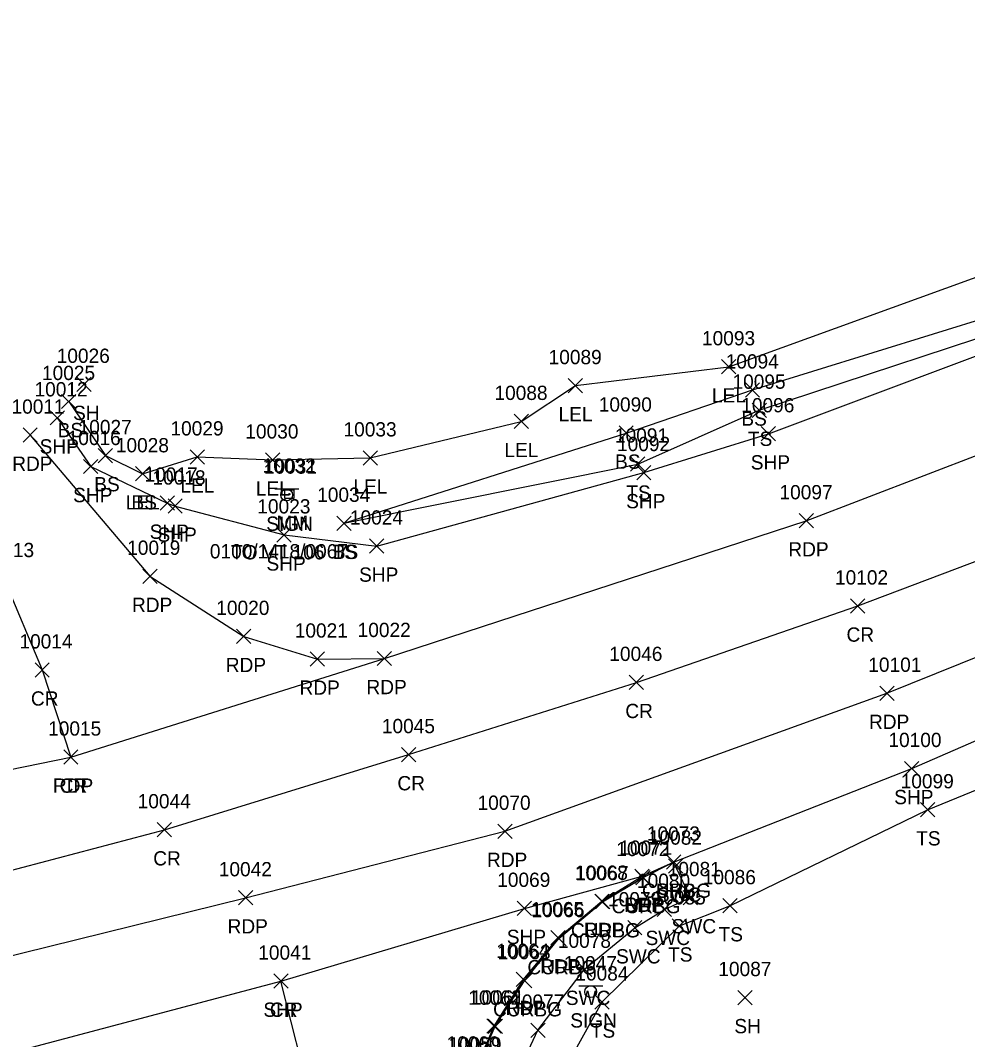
# Model space of a CAD drawing. Extents: x 1611797 to 1633212, y 298978 to 305475.
# Drawn here: x 1631296.3 to 1631428.9, y 304778.9 to 304921.6 of the extents above; entities that cross this region are included whole.
import ezdxf

# ---------------------------------------------------------------- set-up
doc = ezdxf.new("R2010")
doc.units = 0
for name, color, linetype in [('L_A', 7, 'Continuous'), ('L_I', 7, 'Continuous'), ('L_TIC', 7, 'Continuous'), ('LARO', 7, 'Continuous'), ('LELB', 7, 'Continuous'), ('P_A', 7, 'Continuous'), ('P_I', 7, 'Continuous'), ('P_TIC', 7, 'Continuous'), ('PET', 7, 'Continuous'), ('PRC', 7, 'Continuous'), ('PSP', 7, 'Continuous'), ('R_A', 7, 'Continuous'), ('R_I', 7, 'Continuous'), ('R_TIC', 7, 'Continuous'), ('RC', 7, 'Continuous'), ('RSW', 7, 'Continuous'), ('S_A', 7, 'Continuous'), ('S_C', 7, 'Continuous'), ('S_I', 7, 'Continuous'), ('SRM', 7, 'Continuous'), ('SSGN', 7, 'Continuous')]:
    doc.layers.add(name, color=color, linetype=linetype)

msp = doc.modelspace()

# ---------------------------------------------------------------- linework, layer by layer
at = {"layer": 'L_TIC'}
for points in [[(1631394.47, 304872.14), (1631396.47, 304874.14)], [(1631396.47, 304872.14), (1631394.47, 304874.14)], [(1631304.15, 304869.68), (1631306.15, 304871.68)], [(1631306.15, 304869.68), (1631304.15, 304871.68)], [(1631372.99, 304869.5), (1631374.99, 304871.5)], [(1631374.99, 304869.5), (1631372.99, 304871.5)], [(1631397.79, 304868.89), (1631399.79, 304870.89)], [(1631399.79, 304868.89), (1631397.79, 304870.89)], [(1631302.03, 304867.28), (1631304.03, 304869.28)], [(1631304.03, 304867.28), (1631302.03, 304869.28)], [(1631398.74, 304866.06), (1631400.74, 304868.06)], [(1631400.74, 304866.06), (1631398.74, 304868.06)], [(1631365.4, 304864.49), (1631367.4, 304866.49)], [(1631367.4, 304864.49), (1631365.4, 304866.49)], [(1631380.1, 304862.86), (1631382.1, 304864.86)], [(1631382.1, 304862.86), (1631380.1, 304864.86)], [(1631307.16, 304859.7), (1631309.16, 304861.7)], [(1631309.16, 304859.7), (1631307.16, 304861.7)], [(1631320.03, 304859.52), (1631322.03, 304861.52)], [(1631322.03, 304859.52), (1631320.03, 304861.52)], [(1631344.26, 304859.38), (1631346.26, 304861.38)], [(1631346.26, 304859.38), (1631344.26, 304861.38)], [(1631330.59, 304859.09), (1631332.59, 304861.09)], [(1631332.59, 304859.09), (1631330.59, 304861.09)], [(1631381.71, 304858.52), (1631383.71, 304860.52)], [(1631383.71, 304858.52), (1631381.71, 304860.52)], [(1631312.37, 304857.16), (1631314.37, 304859.16)], [(1631314.37, 304857.16), (1631312.37, 304859.16)], [(1631312.37, 304857.16), (1631314.37, 304859.16)], [(1631314.37, 304857.16), (1631312.37, 304859.16)], [(1631340.57, 304850.23), (1631342.57, 304852.23)], [(1631342.57, 304850.23), (1631340.57, 304852.23)], [(1631340.57, 304850.23), (1631342.57, 304852.23)], [(1631342.57, 304850.23), (1631340.57, 304852.23)], [(1631422.31, 304810.12), (1631424.31, 304812.12)], [(1631424.31, 304810.12), (1631422.31, 304812.12)], [(1631394.63, 304796.69), (1631396.63, 304798.69)], [(1631396.63, 304796.69), (1631394.63, 304798.69)], [(1631387.56, 304793.86), (1631389.56, 304795.86)], [(1631389.56, 304793.86), (1631387.56, 304795.86)], [(1631396.76, 304783.83), (1631398.76, 304785.83)], [(1631398.76, 304783.83), (1631396.76, 304785.83)], [(1631376.73, 304783.21), (1631378.73, 304785.21)], [(1631378.73, 304783.21), (1631376.73, 304785.21)]]:
    msp.add_lwpolyline(points, dxfattribs=at)
at = {"layer": 'LARO'}
msp.add_lwpolyline([(1631313.37, 304858.16), (1631321.03, 304860.52), (1631331.59, 304860.09), (1631345.26, 304860.38), (1631366.4, 304865.49), (1631373.99, 304870.5), (1631395.47, 304873.14), (1631433.32, 304886.87), (1631459.67, 304902.4), (1631494.1, 304911.99), (1631530.56, 304929.71), (1631569.34, 304948.13), (1631599.26, 304961.85), (1631641.41, 304983.73), (1631655.76, 304985.84), (1631671.04, 304997.3)], dxfattribs=at)
at = {"layer": 'LELB'}
for points in [[(1631341.57, 304851.23), (1631382.71, 304859.52), (1631399.74, 304867.06), (1631441.68, 304880.89), (1631467.56, 304890.45), (1631498.28, 304903.71), (1631536.55, 304919.94), (1631572.17, 304937.58), (1631605.14, 304953.38), (1631645.02, 304973.23), (1631659.23, 304980.67), (1631701.87, 305003.54), (1631704.19, 305006.88), (1631707.04, 305008.84), (1631710.68, 305036.27), (1631710.46, 305068.61)], [(1631341.57, 304851.23), (1631381.1, 304863.86), (1631398.79, 304869.89), (1631441.05, 304882.98), (1631466.39, 304892.28), (1631497.4, 304904.57), (1631535.71, 304921.45), (1631570.96, 304939.45), (1631603.62, 304955.43), (1631643.84, 304977.06), (1631656.06, 304983.86), (1631700.41, 305004.13), (1631699.04, 305004.95)], [(1631367.17, 304747.85), (1631368.93, 304768.37), (1631377.73, 304784.21), (1631388.56, 304794.86), (1631395.63, 304797.69), (1631423.31, 304811.12), (1631465.4, 304828.31), (1631520.69, 304853.5), (1631557.01, 304870.61), (1631570.25, 304877.09)], [(1631303.03, 304868.28), (1631308.16, 304860.7), (1631313.37, 304858.16)]]:
    msp.add_lwpolyline(points, dxfattribs=at)
at = {"layer": 'P_TIC'}
for points in [[(1631300.41, 304864.99), (1631302.41, 304866.99)], [(1631302.41, 304864.99), (1631300.41, 304866.99)], [(1631296.62, 304862.57), (1631298.62, 304864.57)], [(1631298.62, 304862.57), (1631296.62, 304864.57)], [(1631400.02, 304862.76), (1631402.02, 304864.76)], [(1631402.02, 304862.76), (1631400.02, 304864.76)], [(1631305.1, 304858.18), (1631307.1, 304860.18)], [(1631307.1, 304858.18), (1631305.1, 304860.18)], [(1631382.57, 304857.33), (1631384.57, 304859.33)], [(1631384.57, 304857.33), (1631382.57, 304859.33)], [(1631315.82, 304853.05), (1631317.82, 304855.05)], [(1631317.82, 304853.05), (1631315.82, 304855.05)], [(1631316.93, 304852.64), (1631318.93, 304854.64)], [(1631318.93, 304852.64), (1631316.93, 304854.64)], [(1631405.32, 304850.58), (1631407.32, 304852.58)], [(1631407.32, 304850.58), (1631405.32, 304852.58)], [(1631332.19, 304848.6), (1631334.19, 304850.6)], [(1631334.19, 304848.6), (1631332.19, 304850.6)], [(1631345.16, 304847.04), (1631347.16, 304849.04)], [(1631347.16, 304847.04), (1631345.16, 304849.04)], [(1631313.4, 304842.81), (1631315.4, 304844.81)], [(1631315.4, 304842.81), (1631313.4, 304844.81)], [(1631412.53, 304838.65), (1631414.53, 304840.65)], [(1631414.53, 304838.65), (1631412.53, 304840.65)], [(1631326.53, 304834.39), (1631328.53, 304836.39)], [(1631328.53, 304834.39), (1631326.53, 304836.39)], [(1631336.86, 304831.22), (1631338.86, 304833.22)], [(1631338.86, 304831.22), (1631336.86, 304833.22)], [(1631346.23, 304831.3), (1631348.23, 304833.3)], [(1631348.23, 304831.3), (1631346.23, 304833.3)], [(1631346.23, 304831.3), (1631348.23, 304833.3)], [(1631348.23, 304831.3), (1631346.23, 304833.3)], [(1631298.3, 304829.7), (1631300.3, 304831.7)], [(1631300.3, 304829.7), (1631298.3, 304831.7)], [(1631381.54, 304827.95), (1631383.54, 304829.95)], [(1631383.54, 304827.95), (1631381.54, 304829.95)], [(1631416.62, 304826.43), (1631418.62, 304828.43)], [(1631418.62, 304826.43), (1631416.62, 304828.43)], [(1631302.32, 304817.5), (1631304.32, 304819.5)], [(1631304.32, 304817.5), (1631302.32, 304819.5)], [(1631302.32, 304817.5), (1631304.32, 304819.5)], [(1631304.32, 304817.5), (1631302.32, 304819.5)], [(1631349.63, 304817.84), (1631351.63, 304819.84)], [(1631351.63, 304817.84), (1631349.63, 304819.84)], [(1631420.1, 304815.9), (1631422.1, 304817.9)], [(1631422.1, 304815.9), (1631420.1, 304817.9)], [(1631315.43, 304807.32), (1631317.43, 304809.32)], [(1631317.43, 304807.32), (1631315.43, 304809.32)], [(1631363.11, 304807.11), (1631365.11, 304809.11)], [(1631365.11, 304807.11), (1631363.11, 304809.11)], [(1631386.74, 304802.79), (1631388.74, 304804.79)], [(1631388.74, 304802.79), (1631386.74, 304804.79)], [(1631382.32, 304800.82), (1631384.32, 304802.82)], [(1631384.32, 304800.82), (1631382.32, 304802.82)], [(1631382.32, 304800.82), (1631384.32, 304802.82)], [(1631384.32, 304800.82), (1631382.32, 304802.82)], [(1631326.79, 304797.8), (1631328.79, 304799.8)], [(1631328.79, 304797.8), (1631326.79, 304799.8)], [(1631376.69, 304797.31), (1631378.69, 304799.31)], [(1631378.69, 304797.31), (1631376.69, 304799.31)], [(1631365.84, 304796.32), (1631367.84, 304798.32)], [(1631367.84, 304796.32), (1631365.84, 304798.32)], [(1631370.56, 304792.21), (1631372.56, 304794.21)], [(1631372.56, 304792.21), (1631370.56, 304794.21)], [(1631331.75, 304786.13), (1631333.75, 304788.13)], [(1631333.75, 304786.13), (1631331.75, 304788.13)], [(1631331.75, 304786.13), (1631333.75, 304788.13)], [(1631333.75, 304786.13), (1631331.75, 304788.13)], [(1631365.71, 304786.38), (1631367.71, 304788.38)], [(1631367.71, 304786.38), (1631365.71, 304788.38)], [(1631361.59, 304779.84), (1631363.59, 304781.84)], [(1631363.59, 304779.84), (1631361.59, 304781.84)]]:
    msp.add_lwpolyline(points, dxfattribs=at)
at = {"layer": 'PET'}
for points in [[(1631183.34, 304791.4), (1631232.9, 304801.54), (1631259.87, 304809.61), (1631303.32, 304818.5), (1631347.23, 304832.3), (1631406.32, 304851.58), (1631447.64, 304867.42), (1631474.25, 304878.03), (1631503.98, 304890.8), (1631541.83, 304907.71), (1631577.86, 304925.01), (1631610.67, 304941.1), (1631649.68, 304961.09), (1631665.91, 304969.55), (1631742.05, 305007.18), (1631780.14, 305027.51), (1631792.88, 305033.31), (1631829.98, 305051), (1631869.31, 305070.65), (1631909.86, 305091.12), (1631934.44, 305104.26), (1631965.75, 305123.46), (1631987.63, 305140.55)], [(1631203.79, 304770.25), (1631240.39, 304777.7), (1631272.72, 304785.22), (1631327.79, 304798.8), (1631364.11, 304808.11), (1631417.62, 304827.43), (1631458.87, 304844.05), (1631512.54, 304866.05), (1631551.24, 304883.71), (1631588.3, 304901.31), (1631622.6, 304918.31), (1631660.01, 304936.75), (1631706.66, 304960.79), (1631744.76, 304978.68), (1631787.03, 305001.06), (1631806.21, 305010.59), (1631841.58, 305029.16), (1631879.96, 305048.56), (1631920.69, 305068.82), (1631946.13, 305081.47), (1631980.41, 305098.3)], [(1631297.62, 304863.57), (1631314.4, 304843.81), (1631327.53, 304835.39), (1631337.86, 304832.22), (1631347.23, 304832.3)], [(1631358.43, 304745.88), (1631357.1, 304754.01), (1631357.12, 304760.43), (1631357.65, 304766.1), (1631359.82, 304774.4), (1631362.59, 304780.84), (1631366.71, 304787.38), (1631371.56, 304793.21), (1631377.69, 304798.31), (1631383.32, 304801.82)]]:
    msp.add_lwpolyline(points, dxfattribs=at)
at = {"layer": 'PRC'}
for points in [[(1631200.62, 304781.01), (1631237.62, 304788.44), (1631269.78, 304796.32), (1631289.17, 304801.14), (1631316.43, 304808.32), (1631350.63, 304818.84), (1631382.54, 304828.95), (1631413.53, 304839.65), (1631454.69, 304855.19), (1631506.18, 304877.09), (1631546.86, 304895.1), (1631583.34, 304912.78), (1631616.64, 304929.19), (1631656.09, 304948.53), (1631703.22, 304972.24), (1631736.47, 304989.35), (1631781.29, 305012.13), (1631801.09, 305022.15), (1631835.79, 305039.97), (1631874.72, 305059.56), (1631915.06, 305079.69), (1631940.95, 305092.5), (1631974.43, 305108.96)], [(1631286.36, 304858.45), (1631293.92, 304843.49), (1631299.3, 304830.7), (1631303.32, 304818.5)], [(1631343.84, 304744.37), (1631337.08, 304770.04), (1631332.75, 304787.13)]]:
    msp.add_lwpolyline(points, dxfattribs=at)
at = {"layer": 'PSP'}
for points in [[(1631214.13, 304760.88), (1631250.98, 304766.05), (1631276.49, 304772.06), (1631292.6, 304776.47), (1631332.75, 304787.13), (1631366.84, 304797.32), (1631383.32, 304801.82), (1631387.74, 304803.79), (1631421.1, 304816.9), (1631462.96, 304835.1), (1631515.58, 304858.84), (1631554.35, 304876.64), (1631591.62, 304893.96), (1631626.33, 304910.11), (1631679.82, 304933.94), (1631714.5, 304949.1), (1631757.18, 304970.65), (1631793.91, 304988.76), (1631810.89, 304997.81), (1631847.21, 305017.63), (1631885.01, 305037.47), (1631925.26, 305059.52), (1631950, 305072.86), (1631984.07, 305090.24)], [(1631301.41, 304865.99), (1631306.1, 304859.18), (1631316.82, 304854.05), (1631317.93, 304853.64), (1631333.19, 304849.6), (1631346.16, 304848.04), (1631383.57, 304858.33), (1631401.02, 304863.76), (1631441.98, 304879.1), (1631468.47, 304888.83), (1631500, 304901.31), (1631537.48, 304917.97), (1631573.39, 304935.38), (1631606.01, 304951.47), (1631645.46, 304971.19), (1631660.64, 304978.78), (1631708.39, 305003.93)]]:
    msp.add_lwpolyline(points, dxfattribs=at)
at = {"layer": 'R_TIC'}
for points in [[(1631386.74, 304802.79), (1631388.74, 304804.79)], [(1631388.74, 304802.79), (1631386.74, 304804.79)], [(1631387.03, 304802.23), (1631389.03, 304804.23)], [(1631389.03, 304802.23), (1631387.03, 304804.23)], [(1631382.47, 304800.63), (1631384.47, 304802.63)], [(1631384.47, 304800.63), (1631382.47, 304802.63)], [(1631376.79, 304797.25), (1631378.79, 304799.25)], [(1631378.79, 304797.25), (1631376.79, 304799.25)], [(1631389.1, 304797.82), (1631391.1, 304799.82)], [(1631391.1, 304797.82), (1631389.1, 304799.82)], [(1631385.45, 304796.18), (1631387.45, 304798.18)], [(1631387.45, 304796.18), (1631385.45, 304798.18)], [(1631381.31, 304793.6), (1631383.31, 304795.6)], [(1631383.31, 304793.6), (1631381.31, 304795.6)], [(1631370.69, 304792.08), (1631372.69, 304794.08)], [(1631372.69, 304792.08), (1631370.69, 304794.08)], [(1631374.28, 304787.79), (1631376.28, 304789.79)], [(1631376.28, 304787.79), (1631374.28, 304789.79)], [(1631365.88, 304786.19), (1631367.88, 304788.19)], [(1631367.88, 304786.19), (1631365.88, 304788.19)], [(1631361.77, 304779.82), (1631363.77, 304781.82)], [(1631363.77, 304779.82), (1631361.77, 304781.82)], [(1631367.75, 304779.26), (1631369.75, 304781.26)], [(1631369.75, 304779.26), (1631367.75, 304781.26)]]:
    msp.add_lwpolyline(points, dxfattribs=at)
at = {"layer": 'RC'}
msp.add_lwpolyline([(1631358.52, 304745.92), (1631357.31, 304753.88), (1631357.19, 304760.38), (1631357.76, 304766.14), (1631359.95, 304774.28), (1631362.77, 304780.82), (1631366.88, 304787.19), (1631371.69, 304793.08), (1631377.79, 304798.25), (1631383.47, 304801.63), (1631387.74, 304803.79)], dxfattribs=at)
at = {"layer": 'RSW'}
msp.add_lwpolyline([(1631363.78, 304746.62), (1631362.9, 304754.06), (1631362.95, 304763.35), (1631365.11, 304772.55), (1631368.75, 304780.26), (1631375.28, 304788.79), (1631382.31, 304794.6), (1631386.45, 304797.18), (1631390.1, 304798.82), (1631388.03, 304803.23)], dxfattribs=at)
at = {"layer": 'SRM'}
msp.add_lwpolyline([(1631333.3, 304855.93), (1631334.55, 304855.93), (1631334.55, 304854.68), (1631333.3, 304854.68)], close=True, dxfattribs=at)
msp.add_circle((1631333.93, 304855.31), 0.0833, dxfattribs=at)
at = {"layer": 'SSGN'}
for p, q in [((1631331.91, 304856.03), (1631335.24, 304856.03)), ((1631333.55, 304855.19), (1631333.55, 304855.19)), ((1631374.49, 304786.48), (1631377.82, 304786.48)), ((1631376.13, 304785.65), (1631376.13, 304785.65))]:
    msp.add_line(p, q, dxfattribs=at)
for centre in [(1631333.55, 304855.19), (1631376.13, 304785.65)]:
    msp.add_circle(centre, 0.833, dxfattribs=at)

# ---------------------------------------------------------------- texts
at = {"layer": 'L_A'}
for s, p in [('LEL', (1631393.11, 304868.14)), ('SH', (1631303.63, 304865.68)), ('LEL', (1631371.63, 304865.5)), ('BS', (1631397.23, 304864.89)), ('BS', (1631301.47, 304863.28)), ('TS', (1631398.15, 304862.06)), ('LEL', (1631364.04, 304860.49)), ('BS', (1631379.54, 304858.86)), ('BS', (1631306.6, 304855.7)), ('LEL', (1631318.67, 304855.52)), ('LEL', (1631329.23, 304855.09)), ('LEL', (1631342.9, 304855.38)), ('TS', (1631381.12, 304854.52)), ('LEL', (1631311.01, 304853.16)), ('BS', (1631311.81, 304853.16)), ('TS', (1631339.98, 304846.23)), ('BS', (1631340.01, 304846.23)), ('TS', (1631421.72, 304806.12)), ('TS', (1631394.04, 304792.69)), ('TS', (1631386.97, 304789.86)), ('SH', (1631396.25, 304779.83)), ('TS', (1631376.14, 304779.21))]:
    msp.add_text(s, height=2, dxfattribs=at).set_placement(p)
at = {"layer": 'L_I'}
for s, p in [('10093', (1631391.72, 304876.14)), ('10026', (1631301.34, 304873.68)), ('10089', (1631370.24, 304873.5)), ('10094', (1631395.04, 304872.89)), ('10025', (1631299.28, 304871.28)), ('10095', (1631395.99, 304870.06)), ('10088', (1631362.65, 304868.49)), ('10090', (1631377.26, 304866.86)), ('10027', (1631304.41, 304863.7)), ('10029', (1631317.27, 304863.52)), ('10030', (1631327.76, 304863.09)), ('10033', (1631341.51, 304863.38)), ('10091', (1631379.53, 304862.52)), ('10028', (1631309.62, 304861.16)), ('10028', (1631309.62, 304861.16)), ('10034', (1631337.82, 304854.23)), ('10034', (1631337.82, 304854.23)), ('10099', (1631419.55, 304814.12)), ('10086', (1631391.83, 304800.69)), ('10085', (1631384.81, 304797.86)), ('10084', (1631373.98, 304787.21)), ('10087', (1631394.01, 304787.83))]:
    msp.add_text(s, height=2, dxfattribs=at).set_placement(p)
at = {"layer": 'P_A'}
for s, p in [('SHP', (1631298.95, 304860.99)), ('RDP', (1631295.11, 304858.57)), ('SHP', (1631398.55, 304858.76)), ('SHP', (1631303.64, 304854.18)), ('SHP', (1631381.1, 304853.33)), ('SHP', (1631314.36, 304849.05)), ('SHP', (1631315.46, 304848.64)), ('RDP', (1631403.81, 304846.58)), ('SHP', (1631330.72, 304844.6)), ('SHP', (1631343.69, 304843.04)), ('RDP', (1631311.88, 304838.81)), ('CR', (1631411.96, 304834.65)), ('RDP', (1631325.02, 304830.39)), ('RDP', (1631335.35, 304827.22)), ('RDP', (1631344.72, 304827.3)), ('RDP', (1631344.72, 304827.3)), ('CR', (1631297.73, 304825.7)), ('CR', (1631380.98, 304823.95)), ('RDP', (1631415.11, 304822.43)), ('CR', (1631349.06, 304813.84)), ('RDP', (1631300.81, 304813.5)), ('CR', (1631301.75, 304813.5)), ('SHP', (1631418.64, 304811.9)), ('CR', (1631314.86, 304803.32)), ('RDP', (1631361.6, 304803.11)), ('SHP', (1631385.27, 304798.79)), ('SHP', (1631380.86, 304796.82)), ('RDP', (1631380.81, 304796.82)), ('RDP', (1631325.27, 304793.8)), ('SHP', (1631364.38, 304792.32)), ('RDP', (1631375.18, 304793.31)), ('RDP', (1631369.04, 304788.21)), ('RDP', (1631364.2, 304782.38)), ('SHP', (1631330.29, 304782.13)), ('CR', (1631331.19, 304782.13))]:
    msp.add_text(s, height=2, dxfattribs=at).set_placement(p)
at = {"layer": 'P_I'}
for s, p in [('10012', (1631298.23, 304868.99)), ('10011', (1631295.01, 304866.57)), ('10096', (1631397.22, 304866.76)), ('10016', (1631302.87, 304862.18)), ('10092', (1631379.82, 304861.33)), ('10017', (1631313.64, 304857.05)), ('10018', (1631314.75, 304856.64)), ('10097', (1631402.57, 304854.58)), ('10023', (1631329.44, 304852.6)), ('10024', (1631342.41, 304851.04)), ('10013', (1631290.74, 304846.49)), ('10019', (1631311.21, 304846.81)), ('10102', (1631410.35, 304842.65)), ('10020', (1631323.69, 304838.39)), ('10021', (1631334.68, 304835.22)), ('10022', (1631343.49, 304835.3)), ('10022', (1631343.49, 304835.3)), ('10014', (1631296.12, 304833.7)), ('10046', (1631378.74, 304831.95)), ('10101', (1631415.01, 304830.43)), ('10015', (1631300.14, 304821.5)), ('10015', (1631300.14, 304821.5)), ('10045', (1631346.88, 304821.84)), ('10100', (1631417.83, 304819.9)), ('10044', (1631312.68, 304811.32)), ('10070', (1631360.28, 304811.11)), ('10073', (1631383.99, 304806.79)), ('10071', (1631380.14, 304804.82)), ('10071', (1631380.14, 304804.82)), ('10042', (1631324.04, 304801.8)), ('10068', (1631373.9, 304801.31)), ('10069', (1631363.04, 304800.32)), ('10065', (1631367.76, 304796.21)), ('10041', (1631329.57, 304790.13)), ('10041', (1631329.57, 304790.13)), ('10064', (1631362.91, 304790.38)), ('10061', (1631359.36, 304783.84)), ('10060', (1631355.94, 304777.4))]:
    msp.add_text(s, height=2, dxfattribs=at).set_placement(p)
at = {"layer": 'R_A'}
for s, p in [('CURBG', (1631383.32, 304798.79)), ('SWC', (1631385.39, 304798.23)), ('CURBG', (1631379.05, 304796.63)), ('SWC', (1631387.46, 304793.82)), ('CURBG', (1631373.37, 304793.25)), ('SWC', (1631383.81, 304792.18)), ('SWC', (1631379.68, 304789.6)), ('CURBG', (1631367.27, 304788.08)), ('SWC', (1631372.64, 304783.79)), ('CURBG', (1631362.46, 304782.19))]:
    msp.add_text(s, height=2, dxfattribs=at).set_placement(p)
at = {"layer": 'R_I'}
for s, p in [('10073', (1631383.99, 304806.79)), ('10082', (1631384.28, 304806.23)), ('10072', (1631379.72, 304804.63)), ('10067', (1631373.99, 304801.25)), ('10081', (1631386.92, 304801.82)), ('10080', (1631382.62, 304800.18)), ('10079', (1631378.56, 304797.6)), ('10066', (1631367.84, 304796.08)), ('10078', (1631371.53, 304791.79)), ('10063', (1631363.08, 304790.19)), ('10062', (1631358.98, 304783.82)), ('10077', (1631365, 304783.26)), ('10059', (1631356.2, 304777.28))]:
    msp.add_text(s, height=2, dxfattribs=at).set_placement(p)
at = {"layer": 'S_A'}
for s, p in [('SIGN', (1631330.69, 304850.17)), ('MM', (1631332.12, 304850.31)), ('SIGN', (1631373.27, 304780.63))]:
    msp.add_text(s, height=2, dxfattribs=at).set_placement(p)
at = {"layer": 'S_C'}
for s, p in [('0100/1418/0067', (1631322.79, 304846.31)), ('TO VT 106', (1631325.75, 304846.17))]:
    msp.add_text(s, height=2, dxfattribs=at).set_placement(p)
at = {"layer": 'S_I'}
for s, p in [('10032', (1631330.18, 304858.31)), ('10031', (1631330.35, 304858.17)), ('10047', (1631372.37, 304788.63))]:
    msp.add_text(s, height=2, dxfattribs=at).set_placement(p)

doc.saveas('drawing.dxf')
